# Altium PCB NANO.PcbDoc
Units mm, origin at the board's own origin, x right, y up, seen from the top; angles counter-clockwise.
Board outline 43.18 x 27.94 mm, 2 copper layers (TOP, BOTTOM), stack 1.636 mm thick; 38 components, 38 nets, 184 pads, 59 vias.
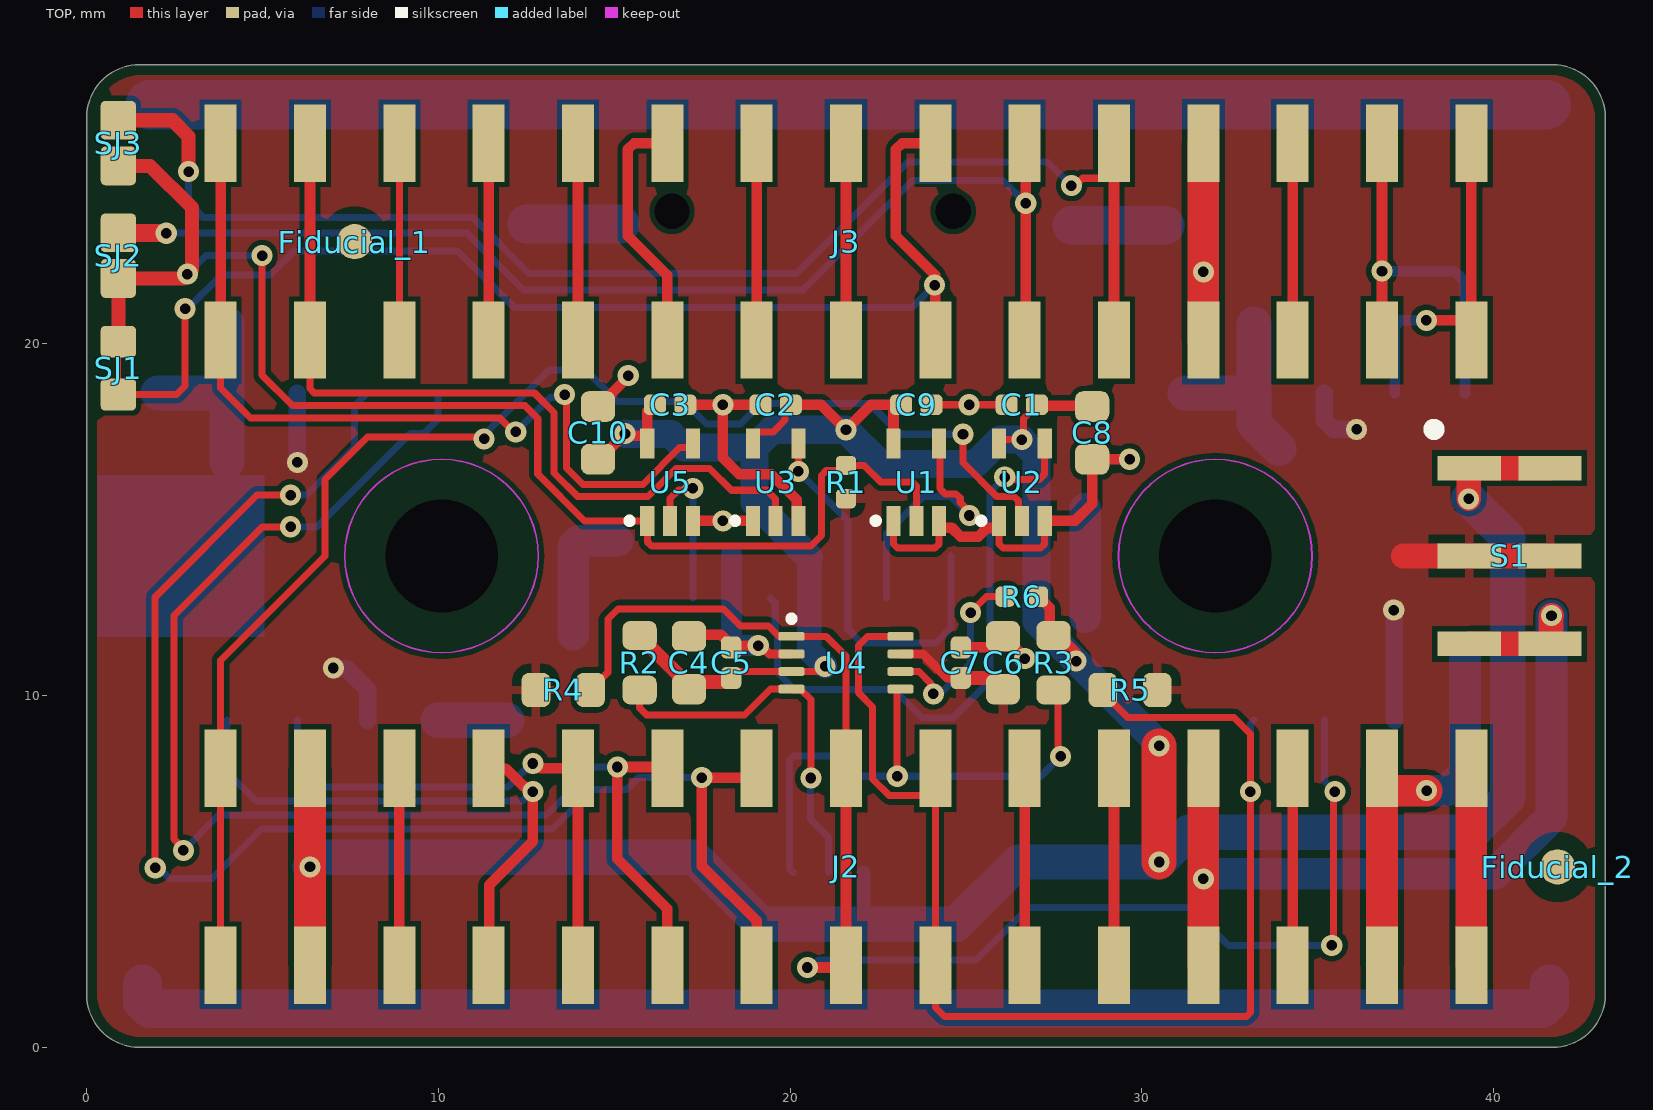
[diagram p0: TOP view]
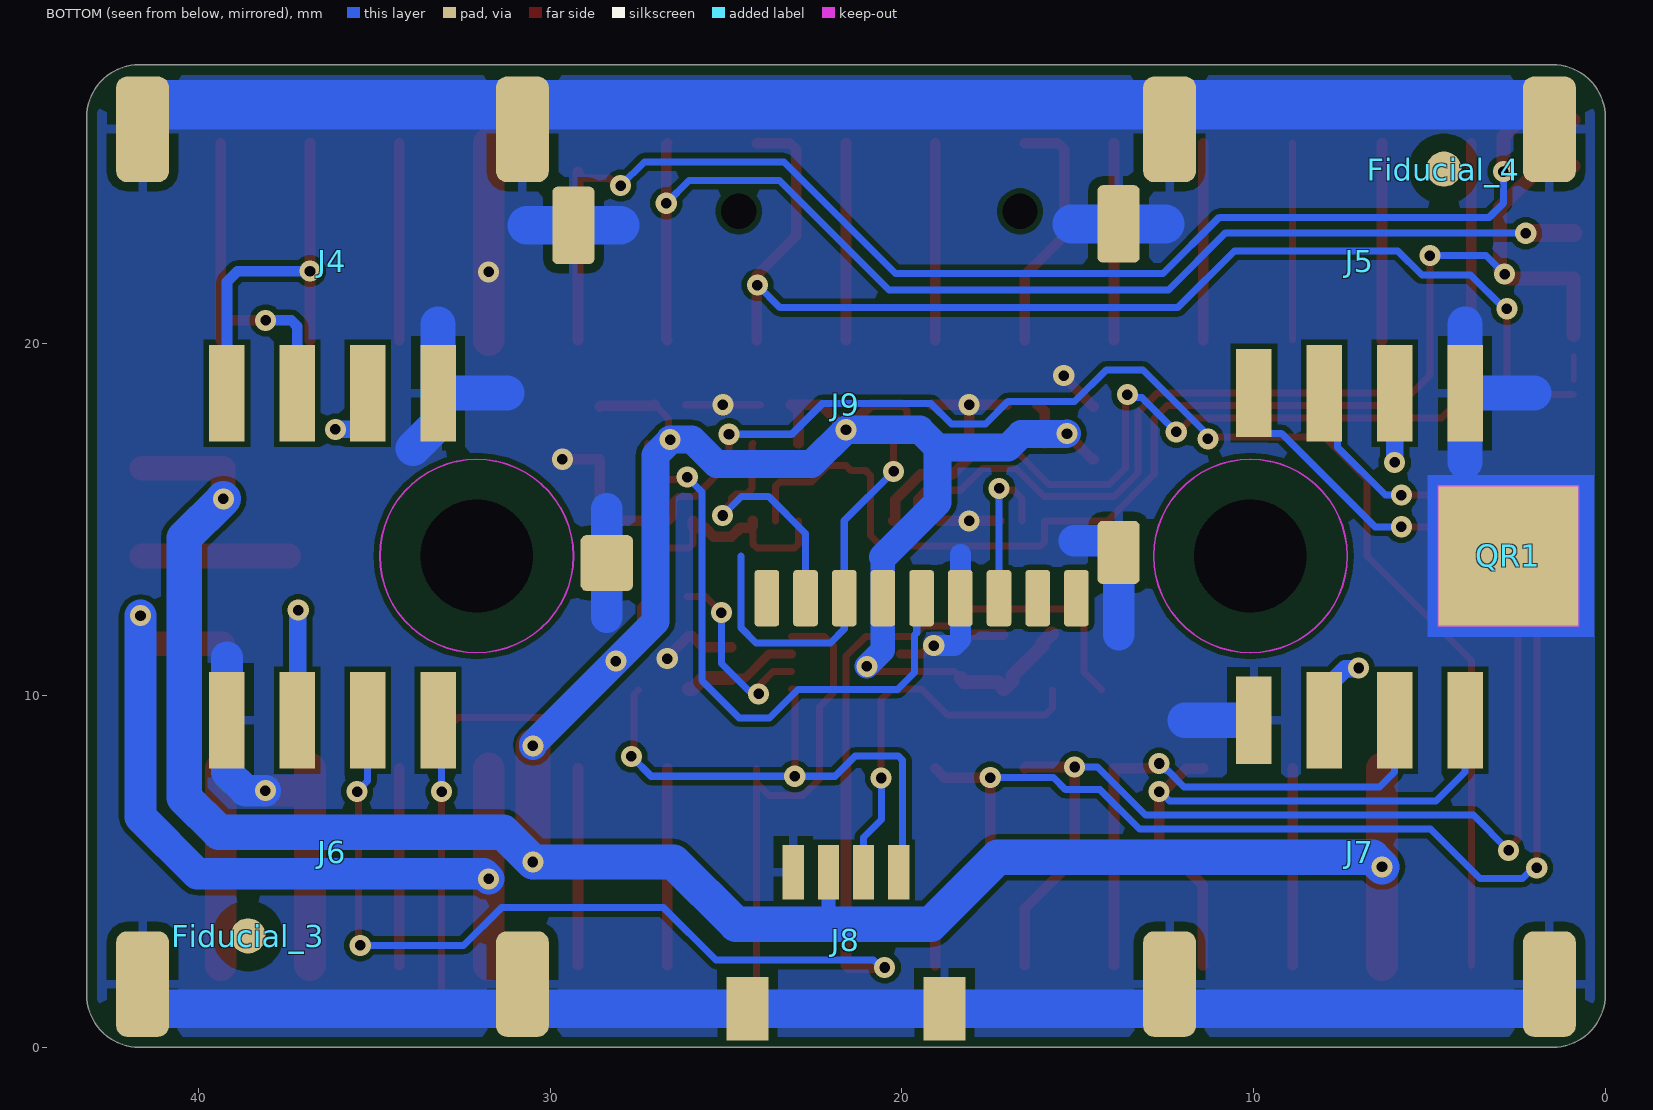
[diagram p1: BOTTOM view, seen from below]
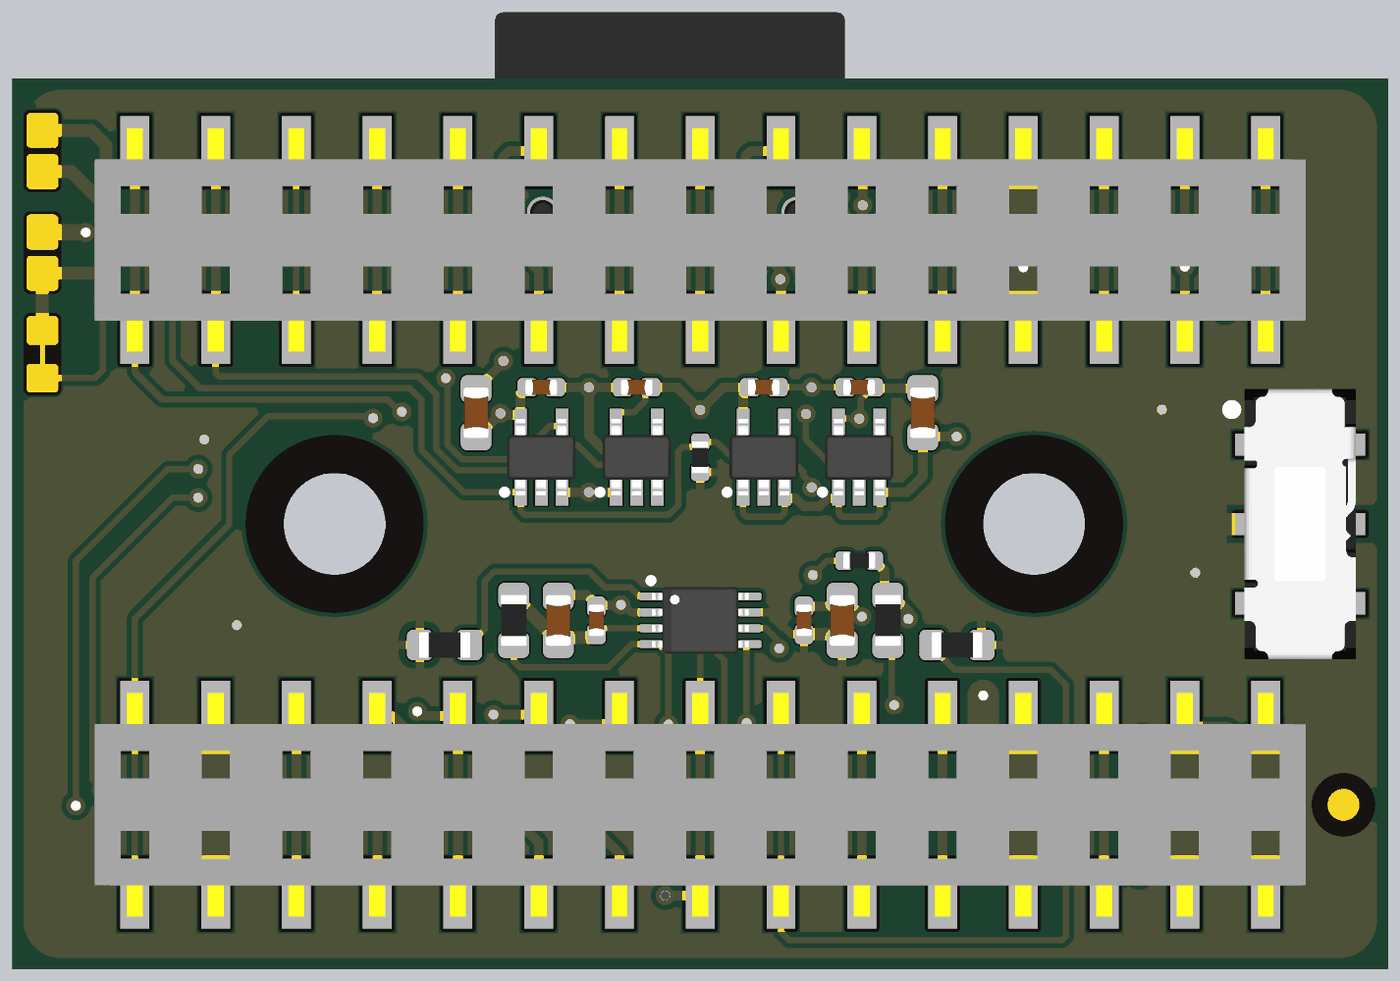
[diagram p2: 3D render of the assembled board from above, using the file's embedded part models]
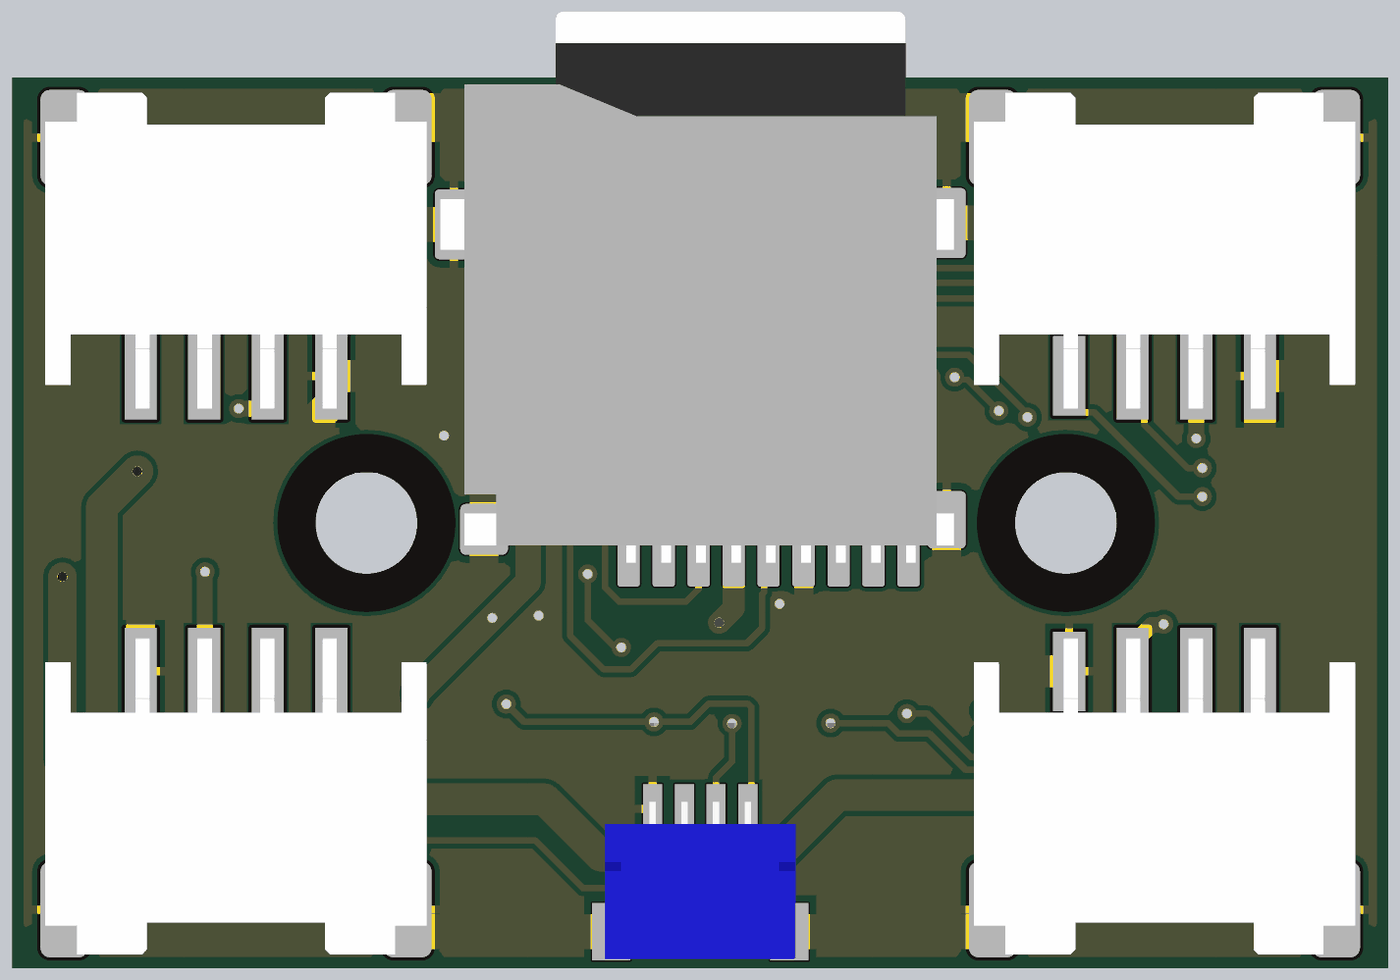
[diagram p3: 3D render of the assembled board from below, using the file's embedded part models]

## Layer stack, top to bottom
Top Solder: solder mask 0.0254, SM-003, Dk 4
TOP: signal copper 0.018
Core: core 1.6, FR-4, Dk 4.8
BOTTOM: signal copper 0.018
Bottom Solder: solder mask 0.0254, SM-003, Dk 4

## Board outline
1.5,0 cw(c1.5,1.5) 0,1.5 0,26.44 cw(c1.5,26.44) 1.5,27.94 41.68,27.94 cw(c41.68,26.44) 43.18,26.44 43.18,1.5 cw(c41.68,1.5) 41.68,0

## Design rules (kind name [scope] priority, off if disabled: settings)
BoardOutlineClearance USBbottomPADS [(ObjectKind = 'Pad') And (Component = 'Free') And (AsMM(PadXSize_AllLayers) = 2.3) And (AsMM(PadYSize_AllLayers) = 1.8)] p1: gap=0 ignorepadtopadclearanceinfootprint=FALSE
BoardOutlineClearance Silks [(OnLayer('Top Overlay') OR OnLayer('Bottom Overlay'))] p2: gap=0 ignorepadtopadclearanceinfootprint=FALSE
BoardOutlineClearance Header_Castellated [((ObjectKind = 'Pad') And (Component = 'J7')) OR                           ((ObjectKind = 'Pad') And (Component = 'J8'))] p3: gap=0 ignorepadtopadclearanceinfootprint=FALSE
BoardOutlineClearance "PADS VBATT_NTC_GND" [(ObjectKind = 'Pad') And (Layer = 'MultiLayer') And (PadShape_AllLayers = 'Rounded Rectangle') And (AsMM(PadYOffset) = 1.5)] p4: gap=0 ignorepadtopadclearanceinfootprint=FALSE
BoardOutlineClearance FILLS_TOP [(ObjectKind = 'Fill') And (Layer = 'TOP') And (AsMM(Y2) = 2.33) OR (AsMM(Y2) = -23.48)] p5: gap=0 ignorepadtopadclearanceinfootprint=FALSE
BoardOutlineClearance FILLS_BOTTOM [(ObjectKind = 'Fill') And (Layer = 'BOTTOM') And (Area = '1.28 sq.')] p6: gap=0 ignorepadtopadclearanceinfootprint=FALSE
BoardOutlineClearance [All] p7: gap=0.3 ignorepadtopadclearanceinfootprint=FALSE except(0.22: SMDPad-OutlineEdge SMDPad-CavityEdge SMDPad-CutoutEdge SMDPad-SplitBarrior SMDPad-SplitContinuation)
Clearance QR [InComponent('QR1') vs InNet('GND')] p1: gap=0 ignorepadtopadclearanceinfootprint=FALSE
Clearance GND_POLYGONS [(InNamedPolygon('GND_TOP') OR InNamedPolygon('GND_2') OR InNamedPolygon('GND_3') OR InNamedPolygon('GND_BOT'))] p2: gap=0.2 ignorepadtopadclearanceinfootprint=FALSE
Clearance "Generic clearance 0.15mm" [All] p3: gap=0.15 ignorepadtopadclearanceinfootprint=FALSE
ComponentClearance FIDUCIALS_CLEARANCE [All vs (ObjectKind = 'Component') And (Comment = 'Fiducial mark 1mm with 2mm solder')] p1: gap=-10 collisioncheckmode=3 verticalgap=-10 showdistances=FALSE
ComponentClearance NINA-UFL [InComponent('U2') vs InComponent('J2')] p2: gap=0 collisioncheckmode=3 verticalgap=0 showdistances=FALSE
ComponentClearance [All] p3: gap=0.2 collisioncheckmode=3 verticalgap=0 showdistances=FALSE
DiffPairsRouting USB [InDifferentialPairClass('USB')] p1: maxlimit=0.15 minlimit=0.15 mostfreqgap=0.15 toplayer_minwidth=0.21 toplayer_maxwidth=0.21 toplayer_prefwidth=0.21 bottomlayer_minwidth=0.21 bottomlayer_maxwidth=0.21 bottomlayer_prefwidth=0.21 impedanceprofiledriven=TRUE impedanceprofileid={674287CF-037A-433D-870D-E878C7318E66} impedanceprofilevalue=90.000000 maxuncoupledlength=12.7
HoleSize [All] p1: absolutevalues=TRUE maxlimit=6 minlimit=0.2 maxpercent=80.000 minpercent=20.000
HoleToHoleClearance [All] p1: gap=0.25 allowstackedmicrovias=TRUE
MinimumAnnularRing MinimumAnnularRing_PADS [(ObjectKind = 'Pad') And (AsMM(HoleDiameter) = 1.016) And (AsMM(SolderMaskExpansion) = 0.2) And (PadShape_AllLayers = 'Round') And (AsMM(PadXSize_AllLayers) = 0.7) And (AsMM(PadYSize_AllLayers) = 0.7) And (Pad_CornerRadius_AllLayers = '50%')] p1: minimumring=0
MinimumAnnularRing [All] p2: minimumring=0.1
MinimumSolderMaskSliver [All] p1: minsoldermaskwidth=0.15
PolygonConnect [All] p1: thpad.connectstyle=Relief thpad.reliefconductorwidth=0.254 thpad.reliefentries=4 thpad.polygonreliefangle="90 Angle" thpad.airgapwidth=0.254 smdpad.connectstyle=Relief smdpad.reliefconductorwidth=0.254 smdpad.reliefentries=4 smdpad.polygonreliefangle="90 Angle" smdpad.airgapwidth=0.254 via.connectstyle=Direct via.reliefconductorwidth=0.254 via.reliefentries=4 via.polygonreliefangle="90 Angle" via.airgapwidth=0.254
RoomDefinition TOP [InComponentClass('TOP')] p1: confinementstyle=ConfineIn formatcopy=TRUE lockcomponents=FALSE outline 46.5,4.2 63.3,4.2 63.3,18.4 46.5,18.4
RoutingVias [All] p1: holewidth=0.3 width=0.6 viastyle="Through Hole" minholewidth=0.3 minwidth=0.6 maxholewidth=0.3 maxwidth=0.6
ShortCircuit ShortCircuit_1 [InNet('NetR1_2') vs InNet('D4_1')] p1: allowed=TRUE
ShortCircuit [All] p2: allowed=FALSE
SilkToSilkClearance [All] p1: silktosilkclearance=0.2
SilkToSolderMaskClearance [IsPad] p1: minsilkscreentomaskgap=0.1 clearancetoexposedcopper=TRUE
SolderMaskExpansion Solder_VIA [IsVia] p1: expansion=0.102 istentingtop=TRUE
SolderMaskExpansion [All] p2: expansion=0.102 istentingtop=FALSE
SupplyNets "Schematic Supply Nets_8" [InNet('VIN')] p1: voltage=0.000
SupplyNets "Schematic Supply Nets_7" [InNet('VSWITCH')] p2: voltage=0.000
SupplyNets "Schematic Supply Nets_5" [InNet('+3V3')] p3: voltage=0.000
SupplyNets "Schematic Supply Nets_3" [InNet('+5V')] p4: voltage=0.000
SupplyNets "Schematic Supply Nets_4" [InNet('GND')] p5: voltage=0.000
UnRoutedNet [All] p1: checkbadconnections=TRUE
ViasUnderSMD [All] p1: allowed=FALSE
Width S50 [InNetClass('SPI')] p1: maxlimit=0.25 minlimit=0.25 preferedwidth=0.25 impedanceprofiledriven=TRUE impedanceprofileid={6EA05C80-3875-4511-9E4A-FB1E634E28F6} impedanceprofilevalue=50.000000 minimp=50.000000 maximp=50.000000 favimp=50.000000
Width [All] p2: maxlimit=5 minlimit=0.15 preferedwidth=0.2
21 further rules are at their usual default settings.

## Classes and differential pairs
component class U_TRANSLATOR_PUSHPULL: C1 C2 C3 C8 C9 C10 U1 U2 U3 U5
component class U_TRANSLATOR_OPENDRAIN: C4 C5 C6 C7 R2 R3 R4 R5 R6 U4
component class TOP: Fiducial_1 Fiducial_2 Fiducial_3 Fiducial_4 J2 J3 QR1 R1 S1 SJ1 SJ2 SJ3
component class U_CONNECTORS: J4 J5 J6 J7 J8 J9
pad class SMDPaste_OFF: FD1-P$1

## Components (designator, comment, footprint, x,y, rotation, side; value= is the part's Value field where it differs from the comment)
C1 "0402B104K160CT" CAP-0402 26.59,18.27 r180 top value=100nF
C2 "0402B104K160CT" CAP-0402 19.59,18.27 r180 top value=100nF
C3 "0402B104K160CT" CAP-0402 16.59,18.27 r0 top value=100nF
C4 "GRM188R61C475KAAJD" CAP-0603 17.125,10.936 r270 top value=4.7µF
C5 "0402B104K160CT" CAP-0402 18.325,10.936 r90 top value=100nF
C6 "GRM188R61C475KAAJD" CAP-0603 26.055,10.936 r270 top value=4.7µF
C7 "0402B104K160CT" CAP-0402 24.855,10.936 r90 top value=100nF
C8 "GRM188R61C475KAAJD" CAP-0603 28.59,17.47 r90 top value=4.7µF
C9 "0402B104K160CT" CAP-0402 23.59,18.27 r0 top value=100nF
C10 "GRM188R61C475KAAJD" CAP-0603 14.54,17.47 r270 top value=4.7µF
Fiducial_1 "Fiducial mark 1mm with 2mm solder" "Fiducial mark 1mm with circle-Footprint-1" 7.62,22.91 r90 top
Fiducial_2 "Fiducial mark 1mm with 2mm solder" "Fiducial mark 1mm with circle-Footprint-1" 41.82,5.13 r90 top
Fiducial_3 "Fiducial mark 1mm with 2mm solder" "Fiducial mark 1mm with circle-Footprint-1" 38.59,3.17 r90 bottom
Fiducial_4 "Fiducial mark 1mm with 2mm solder" "Fiducial mark 1mm with circle-Footprint-1" 4.59,24.97 r0 bottom
J2 "SSM-115-L-DV-P-FR" SSM-115-L-DV-P-FR-Footprint-1 21.59,5.13 r0 top locked
J3 "SSM-115-L-DV-P-FR" SSM-115-L-DV-P-FR-Footprint-1 21.59,22.91 r0 top locked
J4 "320110032" 320110032-Footprint-1#1 36.19,18.7 r180 bottom locked
J5 "320110032" 320110032-Footprint-1#2 6.99,18.7 r180 bottom locked
J6 "320110032" 320110032-Footprint-1#1 36.19,9.2 r0 bottom locked
J7 "320110032" 320110032-Footprint-1#3 6.99,9.2 r0 bottom locked
J8 "SM04B-SRSS-TB(LF)(SN)" SM04B-SRSS-TB(LF)(SN)-Footprint-1 21.59,3.038 r0 bottom locked
J9 "19TW-512" 19TW-512 21.59,23.77 r0 bottom locked
QR1 "QR CODE 4x4mm" "QR CODE 4x4mm" 2.757,13.97 r180 bottom
R1 "CRCW04021K00FKEDC" RES-0402 21.59,16.07 r90 top value=1k
R2 "CRCW060310K0JNEAC" RES-0603 15.725,10.936 r90 top value=10k
R3 "CRCW060310K0JNEAC" RES-0603 27.49,10.936 r90 top value=10k
R4 "CRCW060310K0JNEAC" RES-0603 13.55,10.161 r180 top value=10k
R5 "CRCW060310K0JNEAC" RES-0603 29.665,10.161 r0 top value=10k
R6 "CRCW04021K00FKEDC" RES-0402 26.59,12.813 r0 top value=1k
S1 "IS-2235SJ-G" IS-2235SJ-G 40.456,13.97 r270 top
SJ1 "SOLDER JUMPER CLOSED 0603" "SJ 0603 CLOSED" 0.9,19.31 r270 top
SJ2 "SOLDER JUMPER OPEN 0603" SJ 0.9,22.51 r90 top
SJ3 "SOLDER JUMPER OPEN 0603" SJ 0.9,25.71 r90 top
U1 "SN74LVC1G125DCKR" SC70-5 23.59,16.07 r90 top
U2 "SN74LVC1G125DCKR" SC70-5 26.59,16.07 r90 top
U3 "SN74LVC1G125DCKR" SC70-5 19.59,16.07 r90 top
U4 "TCA9406DCUR" "VSSOP8 pitch 0.5mm body 3.1x2x0.9mm" 21.59,10.936 r0 top
U5 "SN74LVC1G125DCKR" SC70-5 16.59,16.07 r90 top

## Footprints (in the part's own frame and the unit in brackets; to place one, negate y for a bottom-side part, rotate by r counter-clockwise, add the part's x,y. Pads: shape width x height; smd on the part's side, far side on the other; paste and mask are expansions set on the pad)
19TW-512 [mm] "T-FLASH CONNECTOR 08PIN SMT 90°"
  rrect25% 0.7x1.6 smd mask+0.05: 1(2.25,11) 2(1.15,11) 3(0.05,11) 4(-1.05,11) 5(-2.15,11) 6(-3.25,11) 7(-4.35,11) 8(-5.45,11) CD(-6.55,11)
  round 0 hole 1 unplated: 30(-4.95,0) 31(3.05,0)
  rrect25% 1.2x2.2 smd mask+0.05: SH1(7.75,0.4) SH3(-7.75,0.359)
  rrect25% 1.5x1.6 smd mask+0.05: SH2(6.8,10)
  rrect25% 1.2x1.8 smd mask+0.05: SH4(-7.75,9.7)
  body extent -7.98,-6.3 8.17,11.05, height 2
320110032-Footprint-1#1 [mm] "Default PCB Component"
  rect 1.01x2.74 smd: 1(-3,-0.1) 2(-1,-0.1) 3(1,-0.1) 4(3,-0.1)
  rrect40% 1.5x3 smd: SS1(-5.4,7.4) SS2(5.4,7.4)
  body extent -6,-1.14 6,8.81, height 5.01
320110032-Footprint-1#2 [mm] "Default PCB Component"
  rect 1.01x2.5 smd: 1(-3,-0.1)
  rect 1.01x2.74 smd: 2(-1,-0.1) 3(1,-0.1) 4(3,-0.1)
  rrect40% 1.5x3 smd: SS1(-5.4,7.4) SS2(5.4,7.4)
  body extent -6,-1.14 6,8.81, height 5.01
320110032-Footprint-1#3 [mm] "Default PCB Component"
  rect 1.01x2.74 smd: 1(-3,-0.1) 2(-1,-0.1) 3(1,-0.1)
  rect 1.01x2.5 smd: 4(3,-0.1)
  rrect40% 1.5x3 smd: SS1(-5.4,7.4) SS2(5.4,7.4)
  body extent -6,-1.14 6,8.81, height 5.01
CAP-0402 [mm] "Chip Capacitor, 2-Leads, Body  0402 (in) 1005 (mm), IPC Medium Density"
  rrect52% 0.63x0.58 smd mask+0.05: 1(-0.435,0) 2(0.435,0)
  body extent -0.5,-0.25 0.5,0.25, height 0.5
CAP-0603 [mm] "Chip Capacitor, Body 0603 imperial,1.6x0.8mm, IPC High Density"
  rrect51% 0.87x0.97 smd mask+0.05: 1(-0.75,0) 2(0.75,0)
  body extent -0.8,-0.4 0.8,0.4, height 0.8
"Fiducial mark 1mm with circle-Footprint-1" [mm]
  round 1 smd paste-10 mask+0.5: 1(0,0)
  TOP pour cut-out: 0,1 0.383,0.924 0.707,0.707 0.924,0.383 1,0 1,0 0.924,-0.383 0.707,-0.707 0.383,-0.924 0,-1 0,-1 -0.383,-0.924 -0.707,-0.707 -0.924,-0.383 -1,0 -1,0 -0.924,0.383 -0.707,0.707 -0.383,0.924 0,1
IS-2235SJ-G [mm]
  rect 0.7x1.8 smd: 1(-2.5,-1.15) 2(0,-1.15) 3(2.5,-1.15) 4(-2.5,1.15) 5(0,1.15) 6(2.5,1.15)
  silkscreen extent -3.65,-2.2 -3.55,-2.1, body extent -4.25,-1.75 4.25,1.75, height 5.51
"QR CODE 4x4mm" [mm]
  rect 4x4 smd paste-2539.97 mask+0.1: PAD(0,0)
  TOP keep-out region: -2,2 2,2 2,-2 -2,-2
RES-0402 [mm] "Chip Resistor, 2-Leads, Body  0402 (in) 1005 (mm), IPC Medium Density"
  rrect51% 0.55x0.58 smd mask+0.05: 1(-0.475,0) 2(0.475,0)
  body extent -0.5,-0.25 0.5,0.25, height 0.34
RES-0603 [mm] "Chip Resistor - Body 0603 imperial,1.6x0.8mm, IPC High Density"
  rrect51% 0.82x0.97 smd mask+0.05: 1(-0.775,0) 2(0.775,0)
  body extent -0.8,-0.4 0.8,0.4, height 0.43
SC70-5 [mm] "SC70-5/SOT353, 5-Leads, Body 2.00x2.10mm, Pitch 0.65mm, IPC Medium Density"
  rect 0.85x0.4 smd mask+0.05: 1(-1.1,0.65) 2(-1.1,0) 3(-1.1,-0.65) 4(1.1,-0.65) 5(1.1,0.65)
  silkscreen extent -1.15,1.11 -1.05,1.21, body extent -1.2,-1.08 1.2,1.08, height 1.1
SJ [mm]
  rrect25% 1.1x1 smd paste-2539.97 mask+0.1: 1(0.65,0) 2(-0.65,0)
"SJ 0603 CLOSED" [mm]
  rrect25% 0.9x1 smd paste-2539.97 mask+0.1: 1(0.75,0) 2(-0.75,0)
  TOP lines w0.15: 0.35,0 -0.35,0
SM04B-SRSS-TB(LF)(SN)-Footprint-1 [mm]
  rect 0.6x1.55 smd mask+0.05: 1(1.5,-1.937) 2(0.5,-1.937) 3(-0.5,-1.937) 4(-1.5,-1.937)
  rect 1.2x1.8 smd mask+0.05: FIX(-2.8,1.938) FIX(2.8,1.938)
  body extent -3,-2.15 3,2.8, height 2.98
SSM-115-L-DV-P-FR-Footprint-1 [mm]
  rect 0.91x2.2 smd: 1(-17.78,-2.8) 2(-17.78,2.8) 3(-15.24,-2.8) 4(-15.24,2.8) 5(-12.7,-2.8) 6(-12.7,2.8) 7(-10.16,-2.8) 8(-10.16,2.8) 9(-7.62,-2.8) 10(-7.62,2.8) 11(-5.08,-2.8) 12(-5.08,2.8) 13(-2.54,-2.8) 14(-2.54,2.8) 15(0,-2.8) 16(0,2.8) 17(2.54,-2.8) 18(2.54,2.8) 19(5.08,-2.8) 20(5.08,2.8) 21(7.62,-2.8) 22(7.62,2.8) 23(10.16,-2.8) 24(10.16,2.8) 25(12.7,-2.8) 26(12.7,2.8) 27(15.24,-2.8) 28(15.24,2.8) 29(17.78,-2.8) 30(17.78,2.8)
  body extent -19.05,-3.52 19.05,3.52, height 7.44
"VSSOP8 pitch 0.5mm body 3.1x2x0.9mm" [mm] "TSSOP, 8-Leads, Body 2.00x2.30mm, Pitch 0.50mm, IPC High Density"
  rrect50% 0.75x0.25 smd mask+0.05: 1(-1.55,0.75) 2(-1.55,0.25) 3(-1.55,-0.25) 4(-1.55,-0.75) 5(1.55,-0.75) 6(1.55,-0.25) 7(1.55,0.25) 8(1.55,0.75)
  silkscreen extent -1.6,1.2 -1.5,1.3, body extent -1.55,-1.05 1.55,1.05, height 0.9

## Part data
C1 C2 C3 C5 C7 C9: library part C0012-A.15, "CAP CHIP 0402 100nF 10% 16V X7R", Case Code (Imperial)=0402, Dielectric=X7R, Manufacturer=Walsin, Tolerance=10%, Voltage=16V
C4 C6 C8 C10: library part C0054-A.16, "CAP CHIP 0603 4.7uF 10% 16V X5R", Case Code (Imperial)=0603, Dielectric=X5R, Manufacturer=Murata, Manufacturer 3="Samsung Electro-Mechanics", Part number 2=GRM188R61C475KE11D, Part number 3=CL10A475KO8NNNC, Tolerance=10%, Voltage=16V
Fiducial_1 Fiducial_2 Fiducial_3 Fiducial_4: library part UT0024-A.6
J2 J3: library part J0295-A.4, "CONN SOCKET 2ROW 15POS VERTICAL SMD", Manufacturer=Samtech
J4 J5 J6 J7: library part J0274-A.2, "CONN GROVE SMD-90D(4+2P-2.0) 320110032 or 215TW-511", Manufacturer=Seeed, Manufacturer 2=4UCON, Manufacturer Part Number 2=215TW-511
J8: library part J0005-A.2, "CONN JST 4POS SIDE 1MM TIN QWIIC", Manufacturer=JST
J9: library part J0370-A.6, "T-FLASH CONNECTOR 08PIN SMT 90°", Manufacturer=4UCON
QR1: library part QR-0001-A.5, "QR CODE 4x4mm on layer 34 (This is not a component)", Manufacturer="This is not a component"
R1 R6: library part R0007-A.24, "RES CHIP 0402 1k 1% 1/16W", Case Code (Imperial)=0402, Manufacturer=Vishay, Power=62.5mW, Temperature Coefficient=100ppm, Tolerance=1%
R2 R3 R4 R5: library part R0090-A.22, "RES CHIP 0603 10k 5% 1/10W B.5k", Case Code (Imperial)=0603, Manufacturer=Vishay, Power=100mW, Temperature Coefficient=200ppm, Tolerance=5%
S1: library part S0018-A.4, "SWITCH SLIDE DPDT 200mA", Manufacturer=SWITRONIC
SJ1: library part UT0039-A.4
SJ2 SJ3: library part UT0038-A.5
U1 U2 U3 U5: library part U0083-A.9, "IC BUFFER GATE 3-STATE, 1.65V to 5.5V, nOE,  Iout +-24mA, SC70-5 (SOT353)", Manufacturer="Texas Instruments"
U4: library part U0087-A.9, "IC Translator 2b,  Push pull, OE, VCCA 1.65V to 3.6V, VCCB 2.3V to 5.5V, internal 10k pullups, Iq 2uA when VCCA or VCCB at 0V, VSSOP8 3.1x2x0.9mm", Manufacturer="Texas Instruments"

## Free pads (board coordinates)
  round 3 hole 3.2 unplated paste-2539.97 mask+1.3: MH(10.09,13.97) MH(32.09,13.97)

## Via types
v1: diameter 0.6, hole 0.3, TOP to BOTTOM, tented both sides, 59 vias

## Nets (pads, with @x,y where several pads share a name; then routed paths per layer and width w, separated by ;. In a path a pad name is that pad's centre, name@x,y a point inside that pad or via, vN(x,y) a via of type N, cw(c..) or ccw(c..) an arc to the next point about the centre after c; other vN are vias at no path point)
+3V3: C1.1 C2.1 C3.1 C4.2 C5.1 C8.2 C9.1 C10.2 J2.3 J2.4 J8.2 J9.4 R2.2 R3.2 R6.2 S1.1 S1.4 U1.5 U2.5 U3.5 U4.3 U5.5 | length 110.5
  TOP w0.2: C5.1 18.509,10.684 18.631,10.684 18.632,10.686 20.74,10.686 20.887,10.832 v1(20.995,10.832) ; U3.5 18.94,17.389 19.04,17.489 19.51,17.489 19.86,17.839 19.86,18.105 C2.1 ; U2.5 25.94,17.181 26.04,17.281 v1(26.589,17.281) 26.639,17.33 26.639,17.881 27.025,18.268 C1.1
  TOP w0.3: C10.2 14.583,16.72 15.307,17.444 v1(15.307,17.45) 15.364,17.393 15.898,17.393 U5.5@15.94,17.351 ; U5.5 U5.5@15.94,17.351 ; C3.1 16.13,18.27 15.94,18.08 U5.5@15.94,17.351 ; C2.1 20.879,18.27 v1(21.59,17.559) 22.301,18.27 C9.1 23.13,18.27 22.94,18.08 U1.5 ; R6.2@27.019,12.86 27.019,12.845 27.19,12.673 27.205,12.673 27.385,12.493 27.385,11.816 R3.2 ; C1.1 27.05,18.245 28.565,18.245 C8.2
  TOP w0.4: R2.2@15.741,11.76 15.746,11.76 16.004,11.501 16.004,11.414 16.853,10.564 16.853,10.419 17.087,10.186 C4.2 ; C4.2@17.125,10.235 17.283,10.393 18.235,10.393 18.325,10.483 C5.1
  TOP w0.41: R3.2@27.565,11.711 28.096,11.18 28.096,11.017 v1(28.132,10.981)
  TOP w0.7: v1(39.294,15.596) 39.294,16.47 S1.4
  TOP w0.9: J2.3 v1(6.35,5.13) J2.4
  TOP w1: v1(30.49,5.27) v1(30.49,8.57)
  BOTTOM w0.4: 22.09,3.551 J8.2
  BOTTOM w0.7: 20.54,13.944 J9.4 20.54,11.287 v1(20.995,10.832)
  BOTTOM w0.8: v1(15.307,17.45) 15.316,17.441 16.607,17.441 16.99,17.058 18.99,17.058 ; 20.54,13.944 18.99,15.494 18.99,17.058 ; v1(30.49,8.57) 30.49,8.623 v1(28.132,10.981) 27.007,12.106 27.007,16.837 26.589,17.254 v1(26.589,17.281) 25.968,17.281 25.268,16.582 22.567,16.582 v1(21.59,17.559) 19.491,17.559 18.99,17.058
  BOTTOM w1: v1(6.35,5.13) 6.624,5.404 17.276,5.404 19.179,3.5 22.14,3.5 ; 22.09,3.551 22.14,3.5 ; v1(39.294,15.596) 40.406,14.483 40.406,7.106 39.417,6.117 31.337,6.117 v1(30.49,5.27) 26.49,5.27 24.72,3.5 22.14,3.5
+5V: J2.23 J2.24 S1.3 S1.6 | length 25.1
  TOP w0.7: S1.3 S1.6 ; S1.6@41.634,11.47 41.634,12.263 v1(41.649,12.277)
  TOP w0.9: J2.23 J2.24
  BOTTOM w0.9: v1(31.75,4.791) 31.897,4.937 40.037,4.937 41.649,6.549 v1(41.649,12.277)
A0_1: J2.7 J2.8 J7.1 | length 17.6
  TOP w0.3: J2.7 11.441,2.341 11.441,4.61 12.69,5.859 v1(12.69,7.27) 12.609,7.27 12.459,7.42 12.421,7.42 11.922,7.919 11.441,7.919 J2.8
  BOTTOM w0.2: J7.1 3.99,7.83 4.816,7.004 12.39,7.004 12.656,7.27 v1(12.69,7.27)
A1_1: J2.9 J2.10 J7.2 | length 15.6
  TOP w0.3: v1(12.69,8.07) 12.771,8.07 12.911,7.93 J2.10 J2.9
  BOTTOM w0.2: J7.2 5.99,7.83 6.416,7.404 11.976,7.404 12.441,7.87 12.49,7.87 v1(12.69,8.07)
A2_1: J2.11 J2.12 J5.1 | length 38.3
  TOP w0.2: v1(2.75,5.6) 2.75,5.649 2.482,5.917 2.482,12.28 5.002,14.8 v1(5.8,14.8)
  TOP w0.3: J2.11 16.51,3.943 15.09,5.363 v1(15.09,7.97) 16.47,7.97 J2.12
  BOTTOM w0.2: v1(2.75,5.6) 3.754,6.604 13.078,6.604 14.444,7.97 v1(15.09,7.97) ; v1(5.8,14.8) 6.552,14.8 9.202,17.45 9.585,17.45 9.99,17.855 J5.1
A3_1: J2.13 J2.14 J5.2 | length 41.3
  TOP w0.2: v1(1.95,5.1) 1.95,12.802 4.848,15.7 v1(5.8,15.7)
  TOP w0.3: J2.13 19.05,3.595 17.49,5.155 v1(17.49,7.67) 18.79,7.67 J2.14
  BOTTOM w0.2: v1(1.95,5.1) 2.058,5.1 2.358,4.8 3.569,4.8 4.973,6.204 13.243,6.204 14.375,7.336 15.356,7.336 15.69,7.67 v1(17.49,7.67) ; v1(5.8,15.7) 6.253,15.7 7.622,17.069 7.622,18.232 J5.2
A4_SDA_1: J2.15 J2.16 J6.2 R4.1 U4.1 | length 42.2
  TOP w0.2: R4.1 14.325,10.177 14.694,10.546 14.702,10.546 14.819,10.663 14.819,12.179 15.106,12.466 18.111,12.466 18.595,11.981 19.385,11.981 19.68,11.686 U4.1 21.027,11.686 21.59,11.123 J2.16 ; v1(35.4,2.9) 35.445,2.945 35.445,7.225 v1(35.49,7.27)
  TOP w0.3: v1(20.49,2.27) 21.53,2.27 J2.15 J2.16
  BOTTOM w0.2: v1(20.49,2.27) 20.598,2.27 20.807,2.479 25.288,2.479 26.779,3.97 31.39,3.97 32.46,2.9 v1(35.4,2.9) ; J6.2 35.19,7.57 v1(35.49,7.27)
A5_SCL_1: J2.17 J2.18 J6.1 R5.1 U4.8 | length 38.5
  TOP w0.2: U4.8 22.206,11.686 21.94,11.42 21.94,10.083 22.345,9.678 22.345,7.631 22.818,7.157 23.775,7.157 24.13,7.512 J2.18 J2.17 24.13,1.13 24.385,0.875 32.973,0.875 33.09,0.992 v1(33.09,7.27) 33.09,8.905 32.619,9.376 29.6,9.376 28.89,10.086 R5.1
  BOTTOM w0.2: v1(33.09,7.27) 33.09,9.2 J6.1
A6_1: J2.19 J2.20 | length 5.6
  TOP w0.3: J2.19 J2.20
A7_1: J2.21 J2.22 | length 5.6
  TOP w0.3: J2.21 J2.22
AREF_1: J2.5 J2.6 | length 5.6
  TOP w0.3: J2.5 J2.6
B1_1: J2.25 J2.26 | length 5.6
  TOP w0.3: J2.25 J2.26
D0_RX_1: J3.27 J3.28 J4.1 | length 11.3
  TOP w0.3: J3.27 v1(36.83,22.072) J3.28
  BOTTOM w0.3: v1(36.83,22.072) 38.888,22.072 39.19,21.77 J4.1
D1_TX_1: J3.29 J3.30 J4.2 | length 10.1
  TOP w0.3: v1(38.09,20.67) 39.065,20.67 39.37,20.365 J3.29 J3.30
  BOTTOM w0.3: J4.2 37.19,20.494 37.366,20.67 v1(38.09,20.67)
D2_1: J3.21 J3.22 SJ3.1 | length 37.8
  TOP w0.2: v1(28,24.5) 28.108,24.5 28.318,24.71 29.021,24.71 J3.22@29.21,24.899
  TOP w0.3: J3.21 J3.22@29.21,24.899
  TOP w0.4: SJ3.1 2.44,26.36 2.9,25.9 v1(2.9,24.9)
  BOTTOM w0.2: v1(2.9,24.9) 2.9,24 3.3,23.6 10.977,23.6 12.577,22 20.179,22 23.357,25.177 27.323,25.177 v1(28,24.5)
D3_1: J3.19 J3.20 SJ2.1 | length 33.7
  TOP w0.3: SJ2.1 SJ2.1@0.906,23.154 ; v1@2.256,23.154 v1(2.263,23.147) ; J3.19 26.7,20.14 26.7,25.68 J3.20
  TOP w0.5: SJ2.1@0.906,23.154 v1@2.256,23.154
  BOTTOM w0.2: v1(2.263,23.147) 2.276,23.16 10.799,23.16 12.423,21.537 20.367,21.537 23.481,24.65 26.05,24.65 v1(26.7,24)
D4_1: J3.17 J3.18 SJ1.1 | length 35.2
  TOP w0.2: SJ1.1 2.56,18.56 2.8,18.8 v1(2.8,21) ; v1(24.108,21.673) 24.13,21.65 24.108,21.628 24.108,20.767 J3.17@24.13,20.745
  TOP w0.3: J3.17 24.13,20.745 24.13,21.65 24.13,21.95 23.01,23.07 23.01,25.534 23.186,25.71 J3.18
  BOTTOM w0.2: v1(2.8,21) 2.871,21 3.831,21.96 5.218,21.96 5.902,22.644 10.545,22.644 12.161,21.029 23.464,21.029 v1(24.108,21.673)
D5_1: J3.15 J3.16 | length 5.6
  TOP w0.3: J3.15 J3.16
D6_1: J3.13 J3.14 | length 5.6
  TOP w0.3: J3.13 J3.14
D7_1: J3.11 J3.12 | length 7.1
  TOP w0.3: J3.11 16.51,21.95 15.39,23.07 15.39,25.534 15.566,25.71 J3.12
D8_1: J3.9 J3.10 | length 5.6
  TOP w0.3: J3.9 J3.10
D9_1: J3.7 J3.8 | length 5.6
  TOP w0.3: J3.7 J3.8
D10_1: J3.5 J3.6 | length 5.6
  TOP w0.2: J3.5 J3.6
D11_MOSI_1: J3.3 J3.4 U3.2 | length 23.8
  TOP w0.2: J3.3 6.35,18.727 6.467,18.61 12.726,18.61 13.29,18.046 13.29,16.331 13.963,15.658 15.96,15.658 16.76,16.458 17.712,16.458 18.33,15.84 19.345,15.84 19.59,15.595 U3.2
  TOP w0.3: J3.3 J3.4
D12_MISO_1: J3.1 J3.2 U5.4 | length 24.1
  TOP w0.2: J3.1 3.81,18.747 4.663,17.894 11.745,17.894 12.139,17.5 v1(12.2,17.5) ; v1(13.59,18.558) 13.64,18.508 13.64,16.476 14.108,16.008 15.815,16.008 16.857,17.05 17.14,17.05 17.24,17.15 U5.4
  TOP w0.3: J3.1 J3.2
  BOTTOM w0.2: v1(12.2,17.5) 13.182,18.482 13.513,18.482 v1(13.59,18.558)
D13_SCK_1: J2.1 J2.2 U2.2 | length 39.3
  TOP w0.2: J2.1 J2.2 3.81,11.003 6.777,13.97 6.777,16.145 7.99,17.358 11.242,17.358 v1(11.3,17.3) ; v1(24.916,17.432) 24.916,16.625 25.876,15.665 26.366,15.665 26.49,15.541 26.49,15.07 U2.2
  BOTTOM w0.2: v1(11.3,17.3) 11.3,17.408 13.15,19.258 14.19,19.258 15.09,18.358 16.99,18.358 17.628,17.72 18.588,17.72 19.168,18.3 22.265,18.3 23.133,17.432 v1(24.916,17.432)
GND: C1.2 C2.2 C3.2 C4.1 C5.2 C6.1 C7.2 C8.1 C9.2 C10.1 J2.27 J2.28 J3.23 J3.24 J4.4 J4.SS1 J4.SS2 J5.4 J5.SS1 J5.SS2 J6.4 J6.SS1 J6.SS2 J7.4 J7.SS1 J7.SS2 J8.1 J8.FIX J9.6 J9.SH1 J9.SH2 J9.SH3 J9.SH4 QR1.PAD U1.1 U1.3 U2.1 U2.3 U3.1 U3.3 U4.2 U5.3 | length 156.5
  TOP w0.2: U1.1 22.94,14.309 23.057,14.192 24.123,14.192 24.24,14.309 U1.3 ; C9.2 v1(25.09,18.27) C1.2 ; U2.1 25.94,14.309 26.057,14.192 27.123,14.192 27.24,14.309 U2.3
  TOP w0.25: v1@19.175,11.423 19.413,11.186 U4.2
  TOP w0.3: C10.1 14.555,18.22 15.4,19.065 v1(15.4,19.1) ; C3.2 v1(18.09,18.27) ; C4.1@17.125,11.735 18.035,11.735 18.325,11.445 18.325,11.42 18.327,11.422 19.093,11.422 v1(19.094,11.423) v1@19.175,11.423 ; U5.3 v1(18.09,14.97) U3.1 ; C2.2 v1(18.09,18.27) ; U3.3 20.19,15.02 20.19,15.569 19.467,16.291 18.556,16.291 18.09,16.758 v1(18.09,18.27) ; U1.3 24.24,14.829 24.29,14.779 24.59,14.779 24.848,14.521 25.345,14.521 25.59,14.766 25.89,14.766 25.94,14.816 U2.1 ; C7.2 25.651,11.371 25.966,11.686 C6.1 26.072,11.686 26.671,11.087 v1(26.671,11.054) ; U2.3 28.102,14.97 28.59,15.458 C8.1 v1(29.652,16.72)
  TOP w0.9: J3.23 v1(31.75,22.049) J3.24 ; J2.27 J2.28 36.83,7.305 36.835,7.3 v1(38.1,7.3)
  BOTTOM w0.6: J9.6@18.33,12.76 18.33,11.599 18.506,11.423 v1(19.094,11.423) ; J9.6 18.34,14.014
  BOTTOM w0.9: 13.84,11.74 J9.SH4 13.84,14.25 13.99,14.4 15.1,14.4 ; 28.39,12.23 J9.SH2 28.39,15.31 ; v1(38.1,7.3) 38.663,7.3 39.19,7.827 J6.4 39.19,11.093
  BOTTOM w1: 2.029,18.6 J5.4 ; 3.99,16.639 J5.4 ; 3.99,20.561 J5.4 ; J7.4 11.951,9.3 ; 31.229,18.6 J4.4 ; 33.19,20.561 J4.4 ; 33.9,17.025 33.19,17.735 J4.4
  BOTTOM w1.1: J7.SS1 1.59,1.301 1.79,1.1 18.79,1.1 24.39,1.1 41.39,1.1 41.59,1.301 J6.SS2 ; 12.51,23.411 J9.SH3 15.17,23.411 ; 28.01,23.37 J9.SH1 30.67,23.37
  BOTTOM w1.4: J5.SS2@1.8,26.8 12.39,26.8 30.79,26.8 J4.SS1@41.5,26.8
NetJ8_3: J8.3 R2.1 U4.4 | length 11
  TOP w0.2: R2.1 15.725,9.651 15.925,9.451 18.706,9.451 19.441,10.186 U4.4 20.065,10.161 20.315,10.161 20.59,9.886 v1(20.59,7.658)
  BOTTOM w0.2: v1(20.59,7.658) 20.581,7.649 20.581,6.479 21.09,5.97 J8.3
NetJ8_4: J8.4 R3.1 U4.5 | length 16
  TOP w0.2: v1(23.046,7.707) 23.046,10.161 23.071,10.186 U4.5 ; R3.1 27.613,10.037 27.613,8.347 v1(27.69,8.27)
  BOTTOM w0.2: J8.4 19.981,5.085 19.981,8.163 20.098,8.28 21.327,8.28 21.9,7.707 v1(23.046,7.707) 27.127,7.707 v1(27.69,8.27)
NetJ9_2: J9.2 U1.4 | length 7.4
  TOP w0.2: U1.4 24.265,17.145 24.265,15.883 24.412,15.736 24.721,15.736 24.838,15.619 24.838,15.487 25.096,15.229 v1(25.096,15.121)
  BOTTOM w0.2: J9.2 22.74,14.611 23.788,15.659 24.558,15.659 v1(25.096,15.121)
NetJ9_3: J9.3 U3.4 | length 11.2
  TOP w0.2: v1(20.238,16.378) 20.239,16.379 20.239,17.169 U3.4
  BOTTOM w0.2: v1(20.238,16.378) 21.64,14.976 21.64,11.89 22.03,11.5 24.15,11.5 24.582,11.932 24.582,13.97
NetJ9_5: J9.5 U2.4 | length 17.3
  TOP w0.2: v1(26.104,16.215) 26.181,16.138 27.07,16.138 27.24,16.308 U2.4
  BOTTOM w0.2: J9.5 19.579,12.631 19.579,11.787 19.646,11.719 19.646,10.66 20.129,10.178 22.957,10.178 23.766,9.369 24.626,9.369 25.682,10.424 25.682,15.789 26.104,16.211 v1(26.104,16.215)
NetJ9_7: J9.7 U5.2 | length 4.4
  TOP w0.2: U5.2 16.59,15.602 16.833,15.846 17.193,15.846 v1(17.237,15.89)
  BOTTOM w0.2: v1@17.237,15.79 17.239,15.789 17.239,12.771 J9.7
NetR1_2: R1.2 SJ1.2 SJ2.2 SJ3.2 U1.2 U5.1 | length 39.3
  TOP w0.2: SJ1.2@0.9,20.26 SJ1.2@0.95,20.26 ; v1@2.598,21.908 2.788,21.908 v1(2.865,21.985) ; v1(4.99,22.51) 4.99,19.11 5.856,18.244 12.456,18.244 12.825,17.875 12.825,16.301 14.156,14.97 U5.1 15.94,14.375 16.057,14.258 20.59,14.258 20.89,14.558 20.89,16.258 21.027,16.395 21.44,16.395 R1.2 22.103,16.545 22.578,16.07 23.473,16.07 23.59,15.953 U1.2
  TOP w0.4: SJ1.2@0.9,20.26 SJ2.2 2.74,21.86 2.99,22.11 2.99,23.877 1.807,25.06 SJ3.2
  BOTTOM w0.2: v1(2.865,21.985) 3.39,22.51 v1(4.99,22.51)
NetR6_1: R6.1 U4.6 | length 5.4
  TOP w0.2: U4.6 23.663,10.686 23.997,10.352 23.997,10.128 v1(24.073,10.051) ; v1(25.132,12.362) 25.583,12.813 R6.1
  BOTTOM w0.2: v1(24.073,10.051) 24.15,10.128 24.348,10.128 25.132,10.912 v1(25.132,12.362)
nRESET_1: J3.25 J3.26 | length 5.6
  TOP w0.3: J3.25 J3.26
VIN: J2.29 J2.30 | length 5.6
  TOP w0.9: J2.29 J2.30
VSWITCH: C6.2 C7.1 J4.3 J5.3 J6.3 J7.3 R1.1 R4.2 R5.2 S1.2 S1.5 U4.7 | length 16.5
  TOP w0.25: U4.7 23.774,11.186 24.459,10.501 C7.1
  TOP w0.4: C7.1 25.638,10.501 25.953,10.186 C6.2
  TOP w0.7: 37.439,13.97 S1.5
  BOTTOM w0.5: v1(5.99,16.63) J5.3 ; v1(7.015,10.785) 7.034,10.766 7.389,10.766 7.99,10.165 J7.3 ; J4.3 35.19,17.825 35.445,17.57 v1(36.106,17.57) ; v1(37.163,12.433) 37.177,12.42 37.177,9.313 J6.3
pads on no net: Fiducial_1.1 Fiducial_2.1 Fiducial_3.1 Fiducial_4.1 J9.1 J9.8 J9.30 J9.31 J9.CD

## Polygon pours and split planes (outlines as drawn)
GND on BOTTOM "NONET_L04_P-001" (solid, remove dead copper, pour order 1): 0,27.94 0,0 43.18,0 43.18,27.94
VSWITCH on TOP "NONET_L04_P-001" (solid, remove dead copper, pour order 0): 0,27.94 0,0 43.18,0 43.18,27.94

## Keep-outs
Keep-Out Layer:
  circle w0.05: c32.09,13.97 r2.75
  circle w0.05: c10.09,13.97 r2.75

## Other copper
BOTTOM:
  rectangle net GND: 0.31,11.67 5.061,16.27

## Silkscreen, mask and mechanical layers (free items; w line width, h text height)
Route Tool Path:
  lines w2: -1.004,19.02 -1,9.02 ; -1.005,23.02 -1.005,26.44 cw(c1.498,26.437) 1.5,28.94 41.68,28.94 cw(c41.68,26.44) 44.18,26.44 44.18,16.02 ; -1.005,25.52 -1,25.52 ; -1,5.02 -1,1.5 ccw(c1.5,1.5) 1.5,-1 41.68,-1 ccw(c41.68,1.5) 44.18,1.5 44.18,12.02 ; -1,2.52 cw(c0,2.52) -1,2.523 cw(c0,2.527) -1,2.527 ; -1,2.52 ccw(c1.5,2.52) -1,2.517 cw(c0,2.52) -1,2.52 ; -1,2.52 -1,2.527 ; -1,2.527 -1,2.527
Board:
  lines w0.1: 0,1.5 ccw(c1.5,1.5) 1.5,0 41.68,0 ccw(c41.68,1.5) 43.18,1.5 43.18,26.44 ccw(c41.68,26.44) 41.68,27.94 1.5,27.94 ccw(c1.5,26.44) 0,26.44 0,1.5
Nano_outline:
  drawing of 1354 lines, arcs and shapes, not listed
  text "MISO" at 2.862,20.458 h0.4
  text "MOSI" at 5.402,20.458 h0.4
  text "D10" at 7.942,20.458 h0.4
  text "D9" at 10.482,20.458 h0.4
  text "D8" at 13.022,20.458 h0.4
  text "D7" at 15.562,20.458 h0.4
  text "D6" at 18.102,20.458 h0.4
  text "D5" at 20.642,20.458 h0.4
  text "D4" at 23.182,20.458 h0.4
  text "D3" at 25.722,20.458 h0.4
  text "D2" at 28.262,20.458 h0.4
  text "GND" at 30.802,20.458 h0.4
  text "nRESET" at 33.107,20.458 h0.4
  text "RX" at 35.647,20.458 h0.4
  text "TX" at 38.187,20.458 h0.4
  text "USBN" at 2.55,18.98 h0.4
  text "D8 / PIN" at 10.975,18.885 h0.4
  text "D7 / PIN" at 17.5,18.885 h0.4
  text "REV2" at 0.205,18.118 h0.4
  text "GPIO / 29" at 10.975,17.375 h0.4
  text "GPIO / 28" at 17.5,17.375 h0.4
  text "GND" at 38.206,17.085 h0.4
  text "nRESET" at 40.575,17.085 h0.4
  text "REV2" at 0.205,15.578 h0.4
  text "SWCLK" at 38.206,14.545 h0.4
  text "REV2 VUSB" at 0.401,12.53 h0.4
  text "3V3" at 38.206,12.005 h0.4
  text "SWDIO" at 40.746,12.005 h0.4
  text "3V3" at 18.012,11.635 h0.4
  text "3V3 / BUCK / OUT" at 12.538,11.135 h0.4
  text "VUSB" at 32.762,9.785 h0.4
  text "PIN12" at 32.762,8.275 h0.4
  text "A4 / SDA" at 20.407,7.05 h0.4
  text "A5 / SCL" at 22.947,7.05 h0.4
  text "SCK" at 2.627,7.018 h0.4
  text "3V3" at 5.167,7.018 h0.4
  text "AREF" at 7.707,7.018 h0.4
  text "A0" at 10.247,7.018 h0.4
  text "A1" at 12.787,7.018 h0.4
  text "A2" at 15.327,7.018 h0.4
  text "A3" at 17.867,7.018 h0.4
  text "A6" at 25.487,7.018 h0.4
  text "A7" at 28.027,7.018 h0.4
  text "nRESET" at 33.107,7.018 h0.4
  text "GND" at 35.647,7.018 h0.4
  text "VIN" at 38.187,7.018 h0.4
